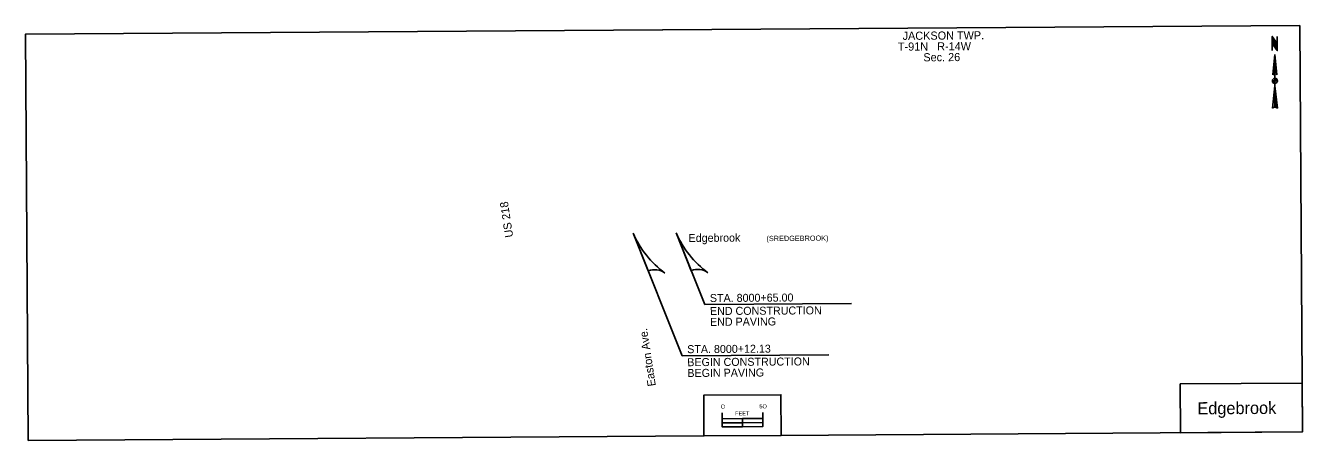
# Model space of a CAD drawing. Extents: x 5197219 to 5260648, y 3686769 to 3705385.
# Drawn here: x 5197219 to 5198790, y 3704874 to 3705385 of the extents above; entities that cross this region are included whole.
import ezdxf

# ---------------------------------------------------------------- set-up
doc = ezdxf.new("R2010")
doc.units = 0
for name, color, linetype in [('dsnCellsScaleBlock', 7, 'Continuous'), ('dsnNonPlotable', 7, 'Continuous'), ('dsnTextNote', 7, 'Continuous'), ('dsnTextOverlapEven', 7, 'Continuous'), ('dsnTextOverlapOdd', 7, 'Continuous'), ('phoTxtTownSecRange', 7, 'Continuous')]:
    doc.layers.add(name, color=color, linetype=linetype)

msp = doc.modelspace()

# ---------------------------------------------------------------- linework, layer by layer
at = {"layer": 'dsnCellsScaleBlock'}
msp.add_line((5198101.1, 3704891.3), (5198101, 3704901.3), dxfattribs=at)
msp.add_line((5198101.1, 3704891.3), (5198101, 3704901.3), dxfattribs=at)
for points in [[(5198053.4, 3704930), (5198148.4, 3704930.6), (5198148.7, 3704880.6), (5198053.7, 3704880)], [(5198053.4, 3704930), (5198148.4, 3704930.6), (5198148.7, 3704880.6), (5198053.7, 3704880)], [(5198076.1, 3704891.1), (5198101.1, 3704891.3), (5198101.1, 3704896.3), (5198076.1, 3704896.2)], [(5198101.1, 3704896.3), (5198126.1, 3704896.5), (5198126, 3704901.5), (5198101, 3704901.3)]]:
    msp.add_lwpolyline(points, close=True, dxfattribs=at)
for points in [[(5198076, 3704908.6), (5198076.1, 3704891.1), (5198126.1, 3704891.5), (5198126, 3704909)], [(5198076, 3704901.1), (5198126, 3704901.5)]]:
    msp.add_lwpolyline(points, dxfattribs=at)
at = {"layer": 'dsnNonPlotable'}
msp.add_lwpolyline([(5198148.7, 3704880.6), (5198148.4, 3704930.6), (5198053.4, 3704930), (5198053.7, 3704880), (5197222.5, 3704874.4), (5197219.1, 3705374.4), (5198786.6, 3705384.9), (5198789.9, 3704884.9)], close=True, dxfattribs=at)
at = {"layer": 'dsnTextNote'}
for p, q in [((5197966.7, 3705129.4), (5198027, 3704978.7)), ((5197985.2, 3705083), (5197966.7, 3705129.4)), ((5197966.9, 3705128.8), (5197966.8, 3705129)), ((5198019.5, 3705129.7), (5198054.8, 3705041.6)), ((5198038.1, 3705083.3), (5198019.5, 3705129.7)), ((5198019.8, 3705129.1), (5198019.7, 3705129.3)), ((5197985.2, 3705083), (5197985.2, 3705083)), ((5198038.1, 3705083.3), (5198038.1, 3705083.3)), ((5198054.8, 3705041.6), (5198235.3, 3705042.8)), ((5198027, 3704978.7), (5198207.4, 3704979.9))]:
    msp.add_line(p, q, dxfattribs=at)
for centre, radius, start, end in [((5198077.6, 3705177.6), 121, 203.5005, 233.5305), ((5198130.5, 3705178), 121, 203.5005, 233.5305), ((5197993.1, 3705063.3), 21.2, 53.5301, 111.8154), ((5198046, 3705063.7), 21.2, 53.5301, 111.8154)]:
    msp.add_arc(centre, radius, start, end, dxfattribs=at)
at = {"layer": 'dsnTextOverlapEven'}
for points in [[(5198789.9, 3704884.9), (5198639.9, 3704883.9), (5198639.5, 3704943.9), (5198789.5, 3704944.9)], [(5198639.5, 3704943.9), (5198789.5, 3704944.9), (5198789.9, 3704884.9), (5198639.9, 3704883.9)]]:
    msp.add_lwpolyline(points, close=True, dxfattribs=at)
at = {"layer": 'dsnTextOverlapOdd'}
for p, q in [((5198755.6, 3705345.1), (5198755.5, 3705343.7)), ((5198752.9, 3705316.8), (5198759.1, 3705316.8)), ((5198753.6, 3705324.5), (5198754, 3705325))]:
    msp.add_line(p, q, dxfattribs=at)
for points in [[(5198752.8, 3705354.1), (5198752.7, 3705371.5)], [(5198759, 3705371.5), (5198759, 3705354.1), (5198752.8, 3705362.8), (5198752.7, 3705371.5), (5198759, 3705362.8)], [(5198753, 3705370.7), (5198753, 3705362.9), (5198758.8, 3705354.8), (5198758.7, 3705362.8), (5198753.3, 3705370.1), (5198753.3, 3705363), (5198758.5, 3705355.7), (5198758.4, 3705362.8), (5198753.5, 3705369.4), (5198753.5, 3705363.1), (5198758.3, 3705356.3), (5198758.1, 3705362.7), (5198753.7, 3705368.7), (5198753.8, 3705363), (5198758.1, 3705356.9), (5198757.8, 3705362.7), (5198753.9, 3705368), (5198753.9, 3705363), (5198757.8, 3705357.7), (5198757.6, 3705362.5), (5198754.1, 3705367.2), (5198754.1, 3705363), (5198757.6, 3705358.6), (5198757.3, 3705362.5), (5198754.4, 3705366.4), (5198754.3, 3705363.1), (5198757.3, 3705359.4), (5198757.1, 3705362.6), (5198754.5, 3705365.7), (5198754.5, 3705363.1), (5198757, 3705360.1), (5198756.7, 3705362.5), (5198754.7, 3705365), (5198754.8, 3705363), (5198756.6, 3705360.7), (5198756.6, 3705362.4), (5198754.9, 3705364.4), (5198754.9, 3705363), (5198756.4, 3705361.3), (5198756.3, 3705362.5), (5198755.2, 3705363.6), (5198755.2, 3705363), (5198756.1, 3705361.9), (5198756.2, 3705362.4), (5198755.4, 3705363.1), (5198755.3, 3705363), (5198755.9, 3705362.3), (5198756, 3705362.4)], [(5198753.5, 3705324.2), (5198755.9, 3705349.1)], [(5198755.8, 3705346.8), (5198755.7, 3705325.7), (5198754.7, 3705325.4), (5198753.8, 3705325), (5198753.7, 3705324.8), (5198755.6, 3705344.5), (5198755.5, 3705325.8), (5198753.9, 3705325.1), (5198755.4, 3705341.8), (5198755.3, 3705325.9), (5198754, 3705325.4), (5198755.3, 3705338.7), (5198755.1, 3705325.9), (5198754.2, 3705325.6), (5198755.1, 3705335.5), (5198754.9, 3705326), (5198754.4, 3705325.8), (5198754.9, 3705332.7), (5198754.7, 3705326.1), (5198754.5, 3705326), (5198754.7, 3705328.5)], [(5198755.9, 3705349.1), (5198756, 3705284.4)], [(5198755.9, 3705349.1), (5198758.4, 3705324.2)], [(5198752.9, 3705316.7), (5198755.9, 3705316.7), (5198755.9, 3705313.8), (5198755.1, 3705313.9), (5198754, 3705314.4), (5198753.4, 3705315.1), (5198753.1, 3705315.8), (5198752.9, 3705316.4), (5198752.9, 3705316.6), (5198752.9, 3705316.6), (5198755.8, 3705316.6), (5198755.9, 3705313.8), (5198754.4, 3705314.1), (5198753.6, 3705314.8), (5198753.2, 3705315.4), (5198753, 3705316.1), (5198752.9, 3705316.6), (5198755.7, 3705316.5), (5198755.8, 3705313.9), (5198755.7, 3705313.7), (5198754.7, 3705314), (5198754.2, 3705314.3), (5198753.6, 3705314.8), (5198753, 3705316.5), (5198755.7, 3705316.5), (5198755.7, 3705313.9), (5198755.8, 3705313.7), (5198755.3, 3705313.8), (5198754.9, 3705313.9), (5198753.4, 3705315.1), (5198753.2, 3705315.5), (5198753, 3705316.2), (5198753.1, 3705316.4), (5198755.6, 3705316.4), (5198755.7, 3705313.9), (5198755.3, 3705313.9), (5198755, 3705313.9), (5198754.3, 3705314.3), (5198753.6, 3705314.9), (5198753.4, 3705315.2), (5198753, 3705316.2), (5198753.1, 3705316.3), (5198755.5, 3705316.3), (5198755.6, 3705313.9), (5198754.5, 3705314.2), (5198753.6, 3705315), (5198753.1, 3705316.2), (5198755.4, 3705316.3), (5198755.5, 3705314), (5198754.5, 3705314.2), (5198753.6, 3705315), (5198753.2, 3705316.2), (5198755.4, 3705316.2), (5198755.4, 3705314), (5198754.5, 3705314.3), (5198753.7, 3705315), (5198753.3, 3705316.1), (5198755.3, 3705316.1), (5198755.4, 3705314.1), (5198754.5, 3705314.3), (5198753.7, 3705315.1), (5198753.4, 3705316), (5198755.3, 3705316), (5198755.3, 3705314.2), (5198754.6, 3705314.4), (5198753.2, 3705315.9), (5198755.2, 3705316), (5198755.3, 3705314.3), (5198754.3, 3705314.6), (5198753.5, 3705315.8), (5198755.1, 3705315.9), (5198755.2, 3705314.3), (5198753.7, 3705315), (5198753.7, 3705315), (5198753.6, 3705315.8), (5198755, 3705315.8), (5198755.1, 3705314.4), (5198754.6, 3705314.4), (5198754, 3705314.8), (5198753.8, 3705315.1), (5198753.7, 3705315.7), (5198754.9, 3705315.7), (5198755, 3705314.5), (5198754.8, 3705314.3), (5198754.4, 3705314.6), (5198753.9, 3705315), (5198753.8, 3705315.6), (5198754.9, 3705315.6), (5198754.9, 3705314.6), (5198754.6, 3705314.5), (5198753.9, 3705315.3), (5198753.8, 3705315.5), (5198754.8, 3705315.6), (5198754.8, 3705314.6), (5198754.1, 3705314.9), (5198753.9, 3705315.4), (5198754.8, 3705315.5), (5198754.8, 3705314.7), (5198754.2, 3705314.9), (5198754, 3705315.4), (5198754.7, 3705315.4)], [(5198754.7, 3705315.4), (5198754.7, 3705314.8), (5198754.2, 3705315), (5198754.1, 3705315.3), (5198754.6, 3705315.3), (5198754.6, 3705314.9), (5198754.3, 3705315), (5198754.2, 3705315.3), (5198754.5, 3705315.3), (5198754.6, 3705315), (5198754.3, 3705315), (5198754.3, 3705315.2), (5198754.5, 3705315.2), (5198754.5, 3705315.1), (5198754.4, 3705315.1), (5198754.4, 3705315.1), (5198754.5, 3705315)], [(5198759, 3705316.8), (5198756, 3705316.8), (5198756, 3705319.8), (5198756.9, 3705319.7), (5198757.9, 3705319.1), (5198758.5, 3705318.4), (5198758.8, 3705317.7), (5198759, 3705317.1), (5198759, 3705316.9), (5198759, 3705316.9), (5198756.1, 3705316.9), (5198756.1, 3705319.7), (5198757.5, 3705319.4), (5198758.3, 3705318.7), (5198758.7, 3705318.1), (5198758.9, 3705317.5), (5198759, 3705316.9), (5198756.2, 3705317), (5198756.1, 3705319.6), (5198756.2, 3705319.8), (5198757.2, 3705319.5), (5198757.7, 3705319.2), (5198758.3, 3705318.7), (5198758.9, 3705317), (5198756.2, 3705317), (5198756.2, 3705319.6), (5198756.1, 3705319.8), (5198756.6, 3705319.7), (5198757, 3705319.6), (5198758.5, 3705318.4), (5198758.7, 3705318), (5198758.9, 3705317.3), (5198758.8, 3705317.1), (5198756.3, 3705317.1), (5198756.2, 3705319.6), (5198756.6, 3705319.7), (5198756.9, 3705319.6), (5198757.6, 3705319.2), (5198758.3, 3705318.6), (5198758.5, 3705318.4), (5198758.9, 3705317.3), (5198758.8, 3705317.2), (5198756.4, 3705317.2), (5198756.3, 3705319.6), (5198757.4, 3705319.3), (5198758.3, 3705318.5), (5198758.8, 3705317.3), (5198756.5, 3705317.3), (5198756.4, 3705319.5), (5198757.4, 3705319.3), (5198758.3, 3705318.5), (5198758.7, 3705317.3), (5198756.5, 3705317.3), (5198756.5, 3705319.5), (5198757.4, 3705319.2), (5198758.2, 3705318.5), (5198758.6, 3705317.4), (5198756.6, 3705317.4), (5198756.5, 3705319.4), (5198757.4, 3705319.2), (5198758.2, 3705318.4), (5198758.5, 3705317.5), (5198756.6, 3705317.5), (5198756.6, 3705319.3), (5198757.3, 3705319.2), (5198758.7, 3705317.6), (5198756.7, 3705317.6), (5198756.6, 3705319.3), (5198757.6, 3705318.9), (5198758.4, 3705317.7), (5198756.8, 3705317.6), (5198756.7, 3705319.2), (5198758.2, 3705318.5), (5198758.2, 3705318.5), (5198758.3, 3705317.8), (5198756.9, 3705317.7), (5198756.8, 3705319.1), (5198757.3, 3705319.1), (5198757.9, 3705318.7), (5198758.1, 3705318.4), (5198758.2, 3705317.8), (5198757, 3705317.8), (5198756.9, 3705319), (5198757.1, 3705319.2), (5198757.5, 3705318.9), (5198758, 3705318.5), (5198758.1, 3705317.9), (5198757, 3705317.9), (5198757, 3705319), (5198757.3, 3705319), (5198758, 3705318.3), (5198758.1, 3705318), (5198757.1, 3705318), (5198757.1, 3705318.9), (5198757.8, 3705318.6), (5198758, 3705318.1), (5198757.1, 3705318.1), (5198757.2, 3705318.8), (5198757.7, 3705318.6), (5198757.9, 3705318.2), (5198757.2, 3705318.1)], [(5198757.2, 3705318.1), (5198757.2, 3705318.7), (5198757.7, 3705318.5), (5198757.8, 3705318.2), (5198757.3, 3705318.2), (5198757.3, 3705318.6), (5198757.6, 3705318.5), (5198757.7, 3705318.3), (5198757.4, 3705318.2), (5198757.4, 3705318.6), (5198757.6, 3705318.5), (5198757.6, 3705318.3), (5198757.4, 3705318.3), (5198757.4, 3705318.4), (5198757.5, 3705318.4), (5198757.5, 3705318.4), (5198757.4, 3705318.5)], [(5198759.1, 3705283.2), (5198756, 3705310.6), (5198752.9, 3705283.2)], [(5198756.1, 3705308.4), (5198756.1, 3705307.3), (5198756.2, 3705307.4), (5198756.1, 3705308.6)], [(5198756.1, 3705306.9), (5198758.7, 3705283.9), (5198756.3, 3705284.6), (5198756.1, 3705307.3), (5198758.9, 3705283.6), (5198757.6, 3705284.8), (5198757.4, 3705284.5), (5198756.6, 3705284.6), (5198757.9, 3705284.2)], [(5198756.3, 3705306), (5198756.4, 3705284.9), (5198757.4, 3705284.6), (5198758.3, 3705284.2), (5198758.5, 3705284), (5198756.4, 3705303.7), (5198756.6, 3705285), (5198758.2, 3705284.4), (5198756.6, 3705301.1), (5198756.8, 3705285.1), (5198758.1, 3705284.6), (5198756.8, 3705297.9), (5198757, 3705285.1), (5198757.9, 3705284.9), (5198757, 3705294.7), (5198757.2, 3705285.2), (5198757.7, 3705285), (5198757.2, 3705291.9), (5198757.4, 3705285.3), (5198757.6, 3705285.2), (5198757.4, 3705287.7)]]:
    msp.add_lwpolyline(points, dxfattribs=at)
msp.add_circle((5198756, 3705316.8), 3.11, dxfattribs=at)
for centre, radius, start, end in [((5198756, 3705322.4), 3.11, 36.9944, 143.2546), ((5198756, 3705279.9), 4.51, 46.5217, 133.7273)]:
    msp.add_arc(centre, radius, start, end, dxfattribs=at)

# ---------------------------------------------------------------- texts
at = {"layer": 'dsnCellsScaleBlock'}
for s, p in [('O', (5198074.3, 3704913.6)), ('FEET', (5198092, 3704905.2)), ('5O', (5198121.9, 3704913.9))]:
    msp.add_text(s, height=5, rotation=0.3814, dxfattribs=at).set_placement(p)
at = {"layer": 'dsnTextNote'}
for s, height, rotation, p in [('US 218', 10, 98.6831, (5197819.1, 3705124.9)), ('Edgebrook', 9.84, 0.3988, (5198034.8, 3705118.6)), ('(SREDGEBROOK)', 6.5, 0.3988, (5198130.6, 3705119.6)), ('STA. 8000+65.00', 9.843, 0.3814, (5198061, 3705044.7)), ('END CONSTRUCTION', 9.843, 0.3814, (5198061.1, 3705028.7)), ('END PAVING', 9.84, 0.3814, (5198061.2, 3705015.4)), ('Easton Ave.', 10, 98.6831, (5197994.5, 3704941.8)), ('STA. 8000+12.13', 9.843, 0.3814, (5198033.1, 3704981.8)), ('BEGIN CONSTRUCTION', 9.843, 0.3814, (5198033.2, 3704965.8)), ('BEGIN PAVING', 9.843, 0.3814, (5198033.3, 3704952.5))]:
    msp.add_text(s, height=height, rotation=rotation, dxfattribs=at).set_placement(p)
at = {"layer": 'dsnTextOverlapEven'}
msp.add_text('Edgebrook', height=15, rotation=0.3814, dxfattribs=at).set_placement((5198660.7, 3704906.5))
at = {"layer": 'phoTxtTownSecRange'}
for s, p in [('JACKSON TWP. ', (5198298.1, 3705367.2)), ('T-91N   R-14W ', (5198292.3, 3705353.9)), ('Sec. 26', (5198323.6, 3705340.8))]:
    msp.add_text(s, height=10, rotation=0.3988, dxfattribs=at).set_placement(p)

doc.saveas('drawing.dxf')
